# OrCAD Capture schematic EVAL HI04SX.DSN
size A; title: EVAL HI03XX; rev: A0; note: 1
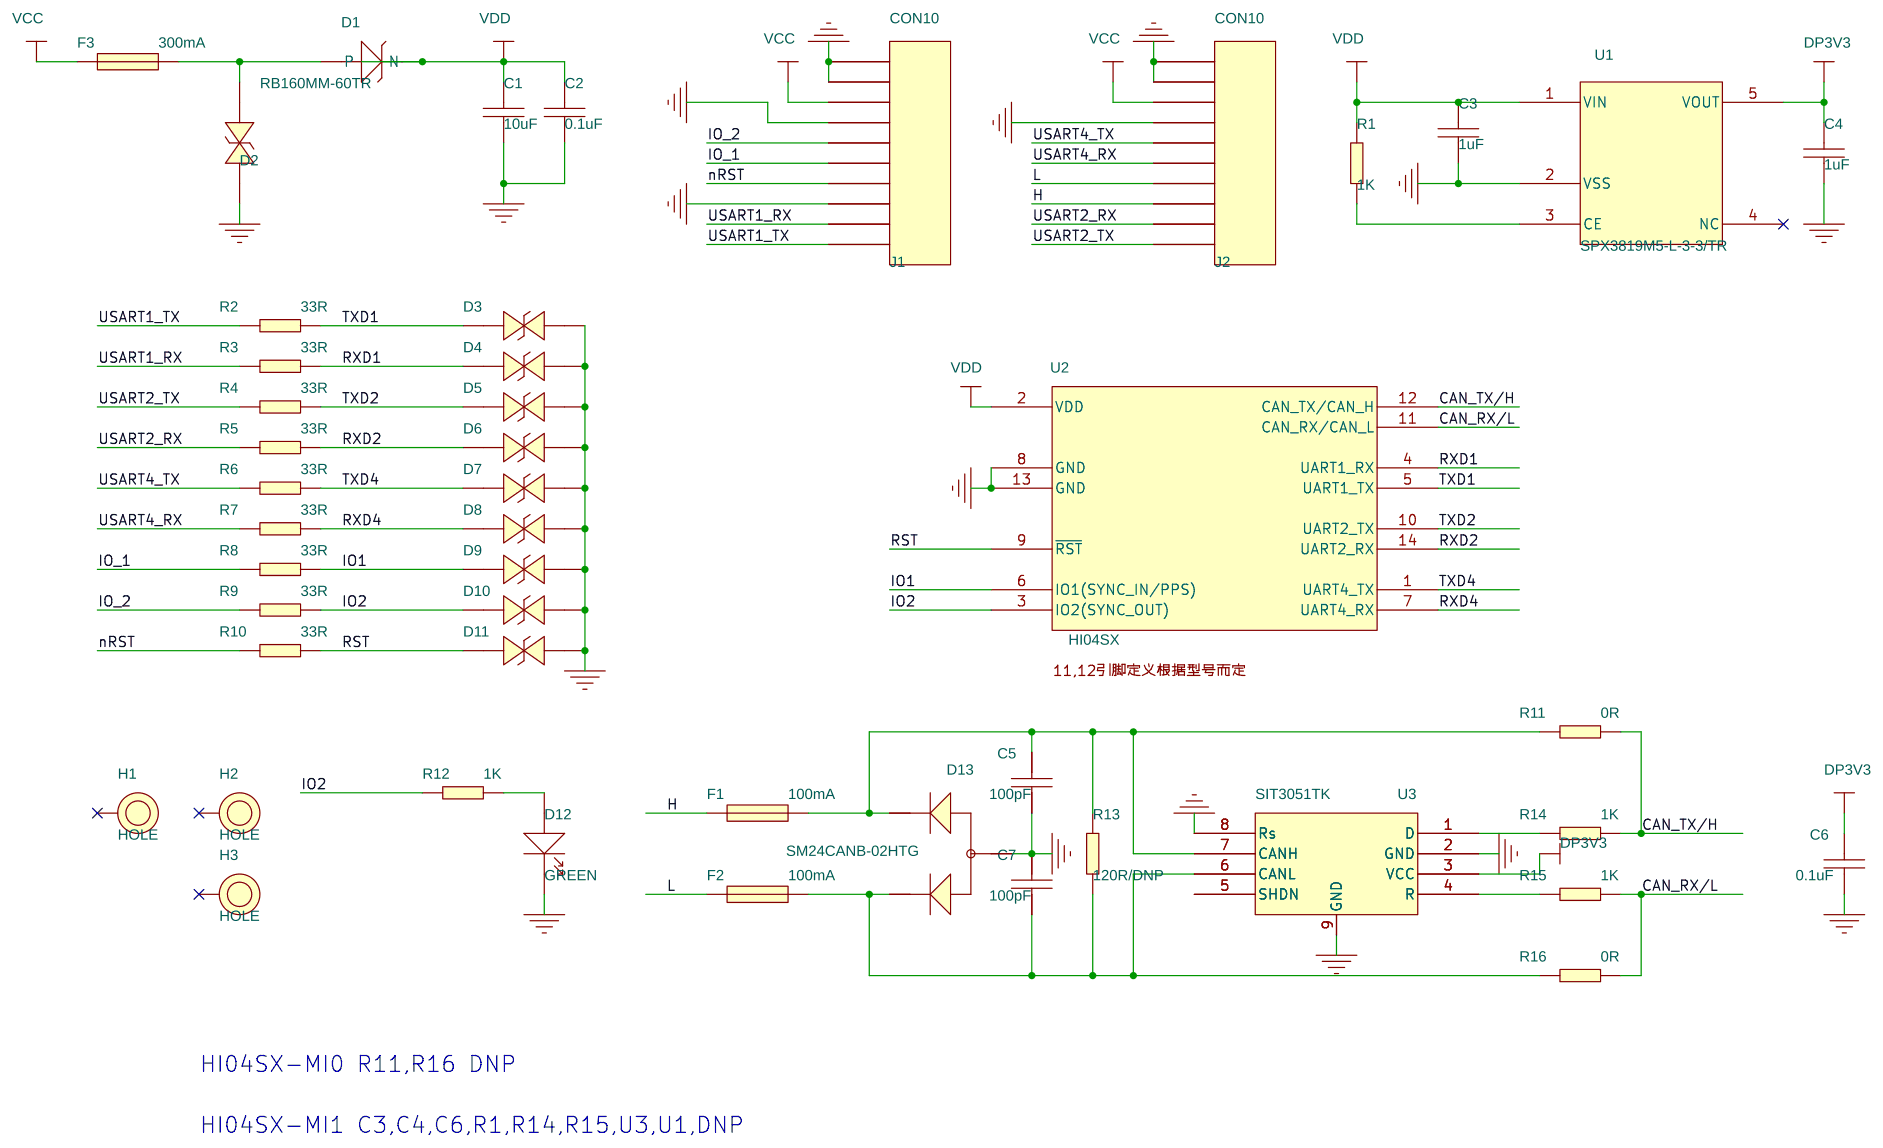
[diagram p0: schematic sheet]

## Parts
C1  10uF  [C0603]
C2  0.1uF  [C0402]
C3  1uF  [C0402]
C4  1uF  [C0402]
C5  100pF  [C0402]
C6  0.1uF  [C0402]
C7  100pF  [C0402]
D1  RB160MM-60TR  [SOD123FL]
D2  SDD32A05L01  [DO-214AC]
D3  SBD52C05L01  [SOD-523]
D4  SBD52C05L01  [SOD-523]
D5  SBD52C05L01  [SOD-523]
D6  SBD52C05L01  [SOD-523]
D7  SBD52C05L01  [SOD-523]
D8  SBD52C05L01  [SOD-523]
D9  SBD52C05L01  [SOD-523]
D10  SBD52C05L01  [SOD-523]
D11  SBD52C05L01  [SOD-523]
D12  GREEN  [LED0402]
D13  SM24CANB-02HTG  [SOT23-3-0_95]
F1  100mA  [F0603]
F2  100mA  [F0603]
F3  300mA  [F0603]
H1  HOLE  [HOLE-2-MM]
H2  HOLE  [HOLE-2-MM]
H3  HOLE  [HOLE-2-MM]
J1  CON10  [5015680807_1]
J2  CON10  [5015680807_1]
R1  1K  [R0402]
R2  33R  [R0402]
R3  33R  [R0402]
R4  33R  [R0402]
R5  33R  [R0402]
R6  33R  [R0402]
R7  33R  [R0402]
R8  33R  [R0402]
R9  33R  [R0402]
R10  33R  [R0402]
R11  0R  [R0402]
R12  1K  [R0402]
R13  120R/DNP  [R0805]
R14  1K  [R0402]
R15  1K  [R0402]
R16  0R  [R0402]
U1  SPX3819M5-L-3-3/TR  [SOT23-5-0_95]
U2  HI04SX  [HI04XX]
U3  SIT3051TK  [HVSON8]

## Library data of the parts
C1-C7 = Capacity_Nonpolarity
D1 = diode
D2-D11 = DIODE_BI-DIR_TRIG
D12 = LED
D13 = BAT54A_SOT
F1-F3 = Fuse
H1-H3 = HOLE
J1 J2 = CON10
R1-R16 = Res
U1 = XC6210
U2 = HI04SX
U3 = SIT3051TK

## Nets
GND: C1.1 C2.1 C3.2 C4.1 C5.2 C6.2 C7.1 D2.1 D3.1 D4.1 D5.1 D6.1 D7.1 D8.1 D9.1 D10.1 D11.1 D12.2(-) D13.3 J1.3 J1.7 J1.9 J1.10 J2.7 J2.9 J2.10 U1.2(VSS) U2.8(GND) U2.13(GND) U3.2(GND) U3.8(Rs) U3.9(GND)
VCC: F3.1 J1.8 J2.8
VDD: C1.2 C2.2 C3.1 D1.2(N) R1.2 U1.1(VIN) U2.2(VDD)
CAN_RX/L: R15.1 R16.1 U2.11(CAN_RX/CAN_L)
CAN_TX/H: R11.1 R14.1 U2.12(CAN_TX/CAN_H)
DP3V3: C4.2 C6.1 U1.5(VOUT) U3.3(VCC)
H: F1.1 J2.3
IO1: D9.2 R8.1 U2.6(IO1(SYNC_IN/PPS))
IO2: D10.2 R9.1 R12.1 U2.3(IO2(SYNC_OUT))
IO_1: J1.5 R8.2
IO_2: J1.6 R9.2
L: F2.1 J2.4
nRST: J1.4 R10.2
RST: D11.2 R10.1 U2.9(~{RST})
RXD1: D4.2 R3.1 U2.4(UART1_RX)
RXD2: D6.2 R5.1 U2.14(UART2_RX)
RXD4: D8.2 R7.1 U2.7(UART4_RX)
TXD1: D3.2 R2.1 U2.5(UART1_TX)
TXD2: D5.2 R4.1 U2.10(UART2_TX)
TXD4: D7.2 R6.1 U2.1(UART4_TX)
USART1_RX: J1.2 R3.2
USART1_TX: J1.1 R2.2
USART2_RX: J2.2 R5.2
USART2_TX: J2.1 R4.2
USART4_RX: J2.5 R7.2
USART4_TX: J2.6 R6.2
N2198535: D12.1(+) R12.2
N2224750: R1.1 U1.3(CE)
N2242059: C5.1 D13.1 F1.2 R11.2 R13.2 U3.7(CANH)
N2242241: R14.2 U3.1(D)
N2242331: C7.2 D13.2 F2.2 R13.1 R16.2 U3.6(CANL)
N2242381: R15.2 U3.4(R)
N2269430: D1.1(P) D2.2 F3.2

Not connected (* = marked no-connect by the designer): H1 1*; H2 1*; H3 1*; U1 4(NC)*; U3 5(SHDN)

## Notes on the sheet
- HI04SX-MI0 R11,R16 DNP
- HI04SX-MI1 C3,C4,C6,R1,R14,R15,U3,U1,DNP
